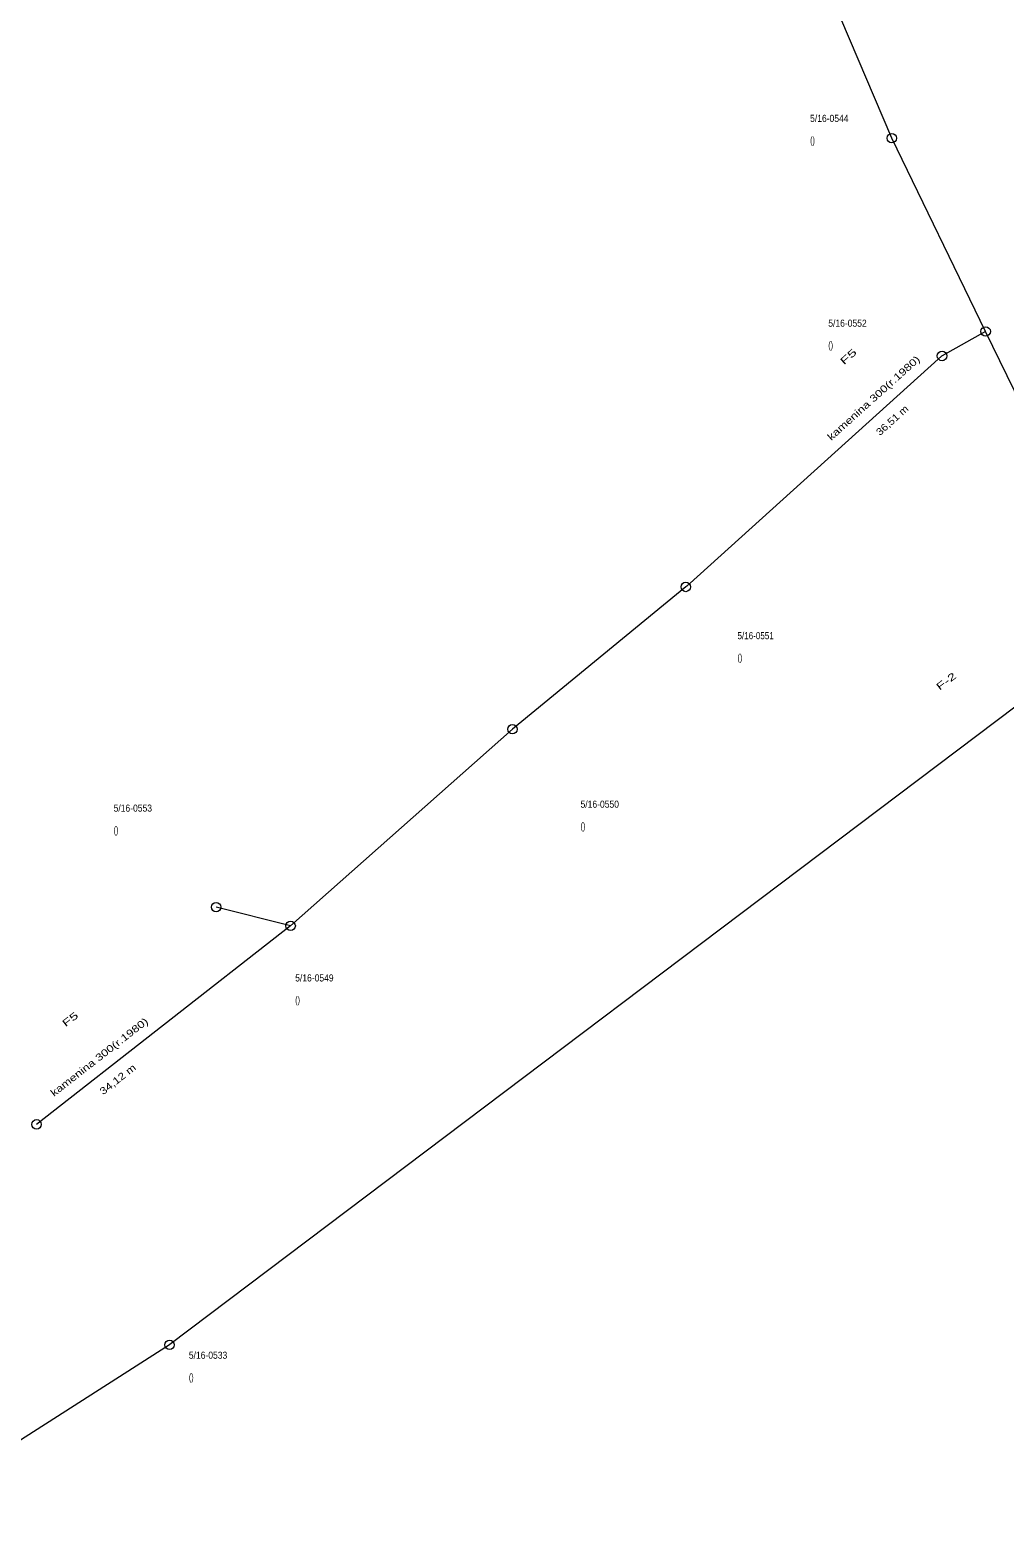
# Model space of a CAD drawing. Extents: x -710854 to -709799, y -1117012 to -1115891.
# Drawn here: x -710724.9 to -710621.7, y -1116883.1 to -1116723.5 of the extents above; entities that cross this region are included whole.
import ezdxf
from ezdxf.enums import TextEntityAlignment as Align

# ---------------------------------------------------------------- set-up
doc = ezdxf.new("R2010")
doc.units = 0
doc.header["$LTSCALE"] = 0.3
doc.layers.add('38', color=7, linetype='Continuous', lineweight=13)
doc.layers.add('44', color=7, linetype='Continuous', lineweight=13)
doc.layers.add('48', color=7, linetype='Continuous')

msp = doc.modelspace()

# ---------------------------------------------------------------- linework, layer by layer
at = {"layer": '38'}
for p, q in [((-710623.76, -1116755.36), (-710628.378, -1116757.956)), ((-710619.203, -1116764.754), (-710623.76, -1116755.36)), ((-710697.3, -1116818.28), (-710705.19, -1116816.29)), ((-710697.3, -1116818.28), (-710724.18, -1116839.29))]:
    msp.add_line(p, q, dxfattribs=at)
for points in [[(-710633.69, -1116734.899), (-710644.497, -1116709.517), (-710644.5, -1116709.51), (-710644.507, -1116709.488)], [(-710623.76, -1116755.36), (-710633.682, -1116734.917), (-710633.69, -1116734.899)], [(-710628.378, -1116757.956), (-710628.42, -1116757.98), (-710628.429, -1116757.989), (-710655.379, -1116782.309), (-710655.38, -1116782.31), (-710655.496, -1116782.405)], [(-710655.496, -1116782.405), (-710673.826, -1116797.458), (-710673.836, -1116797.467)], [(-710616.356, -1116791.882), (-710710.081, -1116862.611), (-710710.107, -1116862.63)], [(-710673.836, -1116797.467), (-710673.84, -1116797.47), (-710697.3, -1116818.28)], [(-710710.107, -1116862.63), (-710710.12, -1116862.64), (-710742.08, -1116883.06)]]:
    msp.add_lwpolyline(points, dxfattribs=at)
at = {"layer": '44'}
for centre in [(-710633.69, -1116734.899), (-710623.76, -1116755.36), (-710628.378, -1116757.956), (-710655.496, -1116782.405), (-710673.836, -1116797.467), (-710705.19, -1116816.29), (-710697.3, -1116818.28), (-710724.18, -1116839.29), (-710710.107, -1116862.63)]:
    msp.add_circle(centre, 0.5, dxfattribs=at)

# ---------------------------------------------------------------- texts
at = {"layer": '48'}
for s, width, p in [('5/16-0544', 0.9, (-710642.334, -1116733.177)), ('()', 0.7, (-710642.334, -1116735.487)), ('5/16-0552', 0.9, (-710640.413, -1116754.861)), ('()', 0.7, (-710640.413, -1116757.171)), ('5/16-0551', 0.85, (-710650.019, -1116787.936)), ('()', 0.7, (-710650.019, -1116790.246)), ('5/16-0553', 0.9, (-710716.032, -1116806.189)), ('5/16-0550', 0.9, (-710666.625, -1116805.777)), ('()', 0.7, (-710716.032, -1116808.499)), ('()', 0.7, (-710666.625, -1116808.087)), ('5/16-0549', 0.9, (-710696.818, -1116824.167)), ('()', 0.7, (-710696.818, -1116826.477)), ('5/16-0533', 0.9, (-710708.072, -1116864.104)), ('()', 0.7, (-710708.072, -1116866.414))]:
    msp.add_text(s, height=0.75, dxfattribs=dict(at, width=width)).set_placement(p)
for s, rotation, width, p in [('F5', 42.06, 1.65, (-710638.0347, -1116758.3048)), ('kamenina 300(r.1980)', 42.06, 1.3, (-710635.3622, -1116762.6824)), ('36,51 m', 42.06, 1.15, (-710633.3942, -1116765.042)), ('F-2', 37.04, 1.55, (-710627.7129, -1116792.6857)), ('F5', 38.01, 1.55, (-710720.3964, -1116828.4645)), ('kamenina 300(r.1980)', 38.01, 1.3, (-710717.3194, -1116832.4556)), ('34,12 m', 38.01, 1.25, (-710715.3619, -1116834.8217))]:
    msp.add_text(s, height=0.75, rotation=rotation, dxfattribs=dict(at, width=width)).set_placement(p, align=Align.CENTER)

doc.saveas('drawing.dxf')
